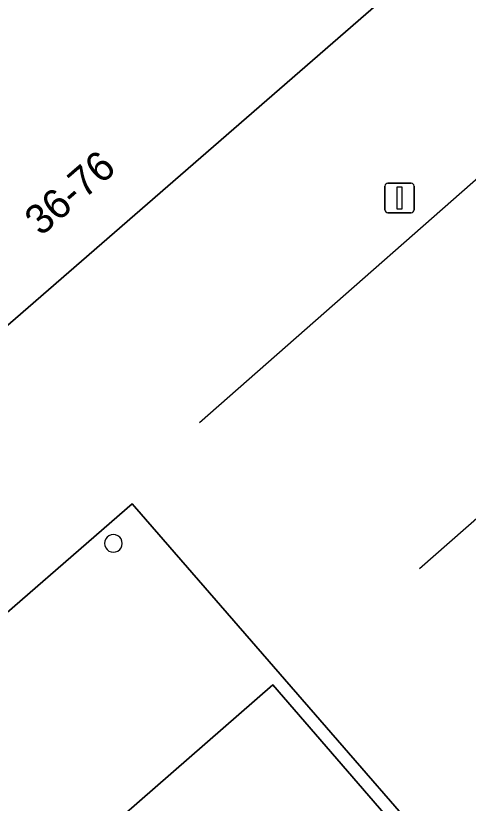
# Model space of a CAD drawing. Extents: x 155640 to 156811, y 382821 to 384049.
# Drawn here: x 156485.33 to 156500.6, y 383776.01 to 383802.6 of the extents above; entities that cross this region are included whole.
import ezdxf

# ---------------------------------------------------------------- set-up
doc = ezdxf.new("R2010")
doc.units = 0
for name, color, linetype in [('IMGEO_Lichtmast', 7, 'Continuous'), ('IMGEO_Lijnafwatering', 7, 'Continuous'), ('IMGEO_Pand', 7, 'Continuous'), ('IMGEO_Pand_nummerreeks', 7, 'Continuous'), ('IMGEO_Pand_overbouw', 7, 'Continuous'), ('IMGEO_Voetgangersgebied_open', 7, 'Continuous'), ('IMGEO_Voetpad_open', 7, 'Continuous')]:
    doc.layers.add(name, color=color, linetype=linetype)

msp = doc.modelspace()

# ---------------------------------------------------------------- linework, layer by layer
at = {"layer": 'IMGEO_Lichtmast'}
for p, q in [((156497.783, 383796.048), (156497.783, 383796.848)), ((156497.783, 383796.848), (156497.783, 383796.048)), ((156497.883, 383796.948), (156498.673, 383796.948)), ((156498.673, 383796.948), (156497.883, 383796.948)), ((156498.773, 383796.848), (156498.773, 383796.048)), ((156498.773, 383796.048), (156498.773, 383796.848)), ((156498.673, 383795.948), (156497.883, 383795.948)), ((156497.883, 383795.948), (156498.673, 383795.948))]:
    msp.add_line(p, q, dxfattribs=at)
msp.add_lwpolyline([(156498.203, 383796.823), (156498.353, 383796.823), (156498.353, 383796.073), (156498.203, 383796.073), (156498.203, 383796.823)], dxfattribs=at)
for centre, start, end in [((156497.883, 383796.848), 90, 180), ((156497.883, 383796.848), 90, 180), ((156498.673, 383796.848), 0, 90), ((156498.673, 383796.848), 360, 90), ((156497.883, 383796.048), 180, 270), ((156497.883, 383796.048), 180, 270), ((156498.673, 383796.048), 270, 0), ((156498.673, 383796.048), 270, 0)]:
    msp.add_arc(centre, 0.1, start, end, dxfattribs=at)
at = {"layer": 'IMGEO_Lijnafwatering'}
for points in [[(156504.298, 383800.086), (156491.532, 383788.854)], [(156498.948, 383783.937), (156510.908, 383794.443)]]:
    msp.add_lwpolyline(points, dxfattribs=at)
at = {"layer": 'IMGEO_Pand'}
msp.add_lwpolyline([(156473.434, 383803.968), (156475.005, 383802.099), (156470.168, 383797.898), (156470.125, 383797.86), (156469.01, 383799.114), (156468.556, 383798.7), (156468.448, 383798.602), (156468.974, 383798.024), (156463.557, 383793.358), (156473.48, 383782.1), (156499.367, 383804.6)], dxfattribs=at)
msp.add_lwpolyline([(156497.967, 383775.43), (156494.004, 383780.006), (156484.378, 383771.622), (156484.208, 383771.362), (156484.606, 383770.903), (156491.34, 383763.141), (156499.415, 383770.147), (156496.178, 383773.878)], close=True, dxfattribs=at)
for centre, radius, start, end in [((156488.621, 383784.787), 0.3, 359.9633, 120), ((156488.62, 383784.788), 0.299, 119.9411, 240.0589), ((156488.622, 383784.786), 0.299, 239.7135, 0.1322)]:
    msp.add_arc(centre, radius, start, end, dxfattribs=at)
at = {"layer": 'IMGEO_Pand_overbouw'}
msp.add_lwpolyline([(156522.244, 383748.131), (156489.331, 383786.036), (156489.254, 383786.124), (156477.703, 383776.08), (156477.589, 383775.981), (156481.391, 383771.435), (156483.001, 383769.51), (156484.606, 383770.903), (156484.208, 383771.362), (156484.378, 383771.622), (156494.004, 383780.006), (156497.967, 383775.43), (156496.178, 383773.878), (156499.415, 383770.147), (156491.34, 383763.141), (156495.141, 383758.761), (156496.961, 383761.545), (156504.403, 383768.001), (156526.125, 383742.921)], dxfattribs=at)
at = {"layer": 'IMGEO_Voetgangersgebied_open'}
msp.add_lwpolyline([(156499.367, 383804.6), (156473.48, 383782.1), (156463.557, 383793.358), (156460.001, 383788.093), (156471.098, 383780.883), (156477.589, 383775.981), (156477.703, 383776.08), (156489.254, 383786.124), (156489.331, 383786.036), (156522.244, 383748.131)], dxfattribs=at)
at = {"layer": 'IMGEO_Voetpad_open'}
msp.add_lwpolyline([(156522.244, 383748.131), (156489.331, 383786.036), (156489.254, 383786.124), (156477.703, 383776.08), (156477.589, 383775.981), (156481.391, 383771.435), (156483.001, 383769.51), (156484.208, 383771.362), (156484.378, 383771.622), (156494.004, 383780.006), (156497.967, 383775.43), (156504.403, 383768.001), (156526.125, 383742.921)], dxfattribs=at)
for centre, radius, start, end in [((156488.621, 383784.787), 0.3, 359.9633, 120), ((156488.62, 383784.788), 0.299, 119.9411, 240.0589), ((156488.622, 383784.786), 0.299, 239.7135, 0.1322)]:
    msp.add_arc(centre, radius, start, end, dxfattribs=at)

# ---------------------------------------------------------------- texts
at = {"layer": 'IMGEO_Pand_nummerreeks'}
msp.add_text('36-76', height=1, rotation=40.8003, dxfattribs=at).set_placement((156486.176, 383795.134))

doc.saveas('drawing.dxf')
